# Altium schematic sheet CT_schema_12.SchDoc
size 278 x 170 mm
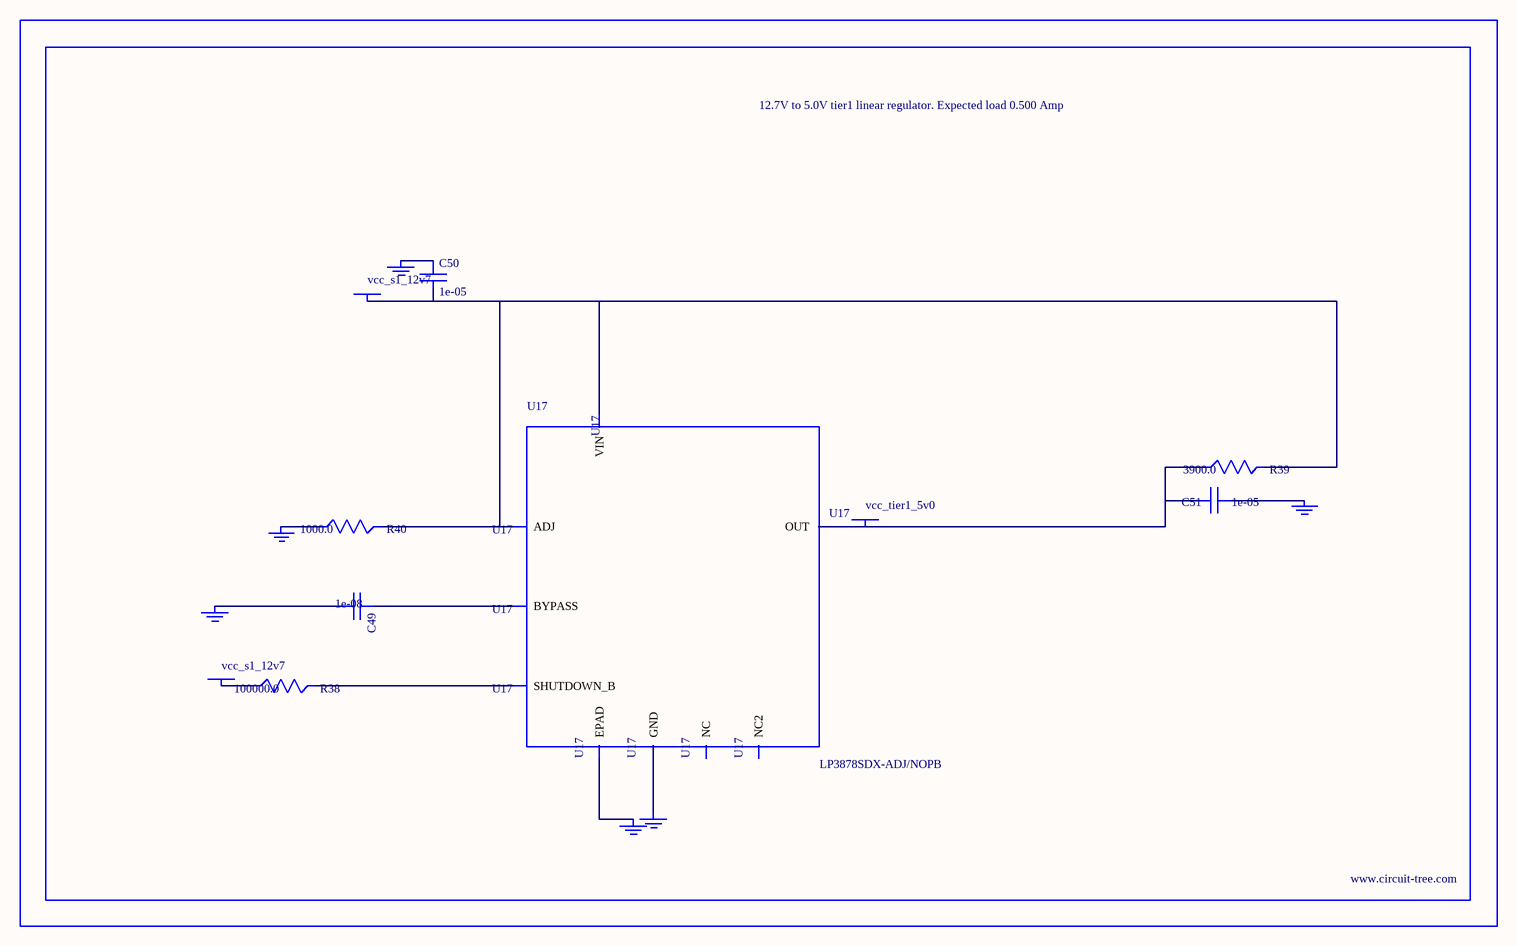
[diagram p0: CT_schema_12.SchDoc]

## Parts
BORDER11  (no value)
C49  1e-08  [C0402]
C50  1e-05  [C1210]
C51  1e-05  [C1210]
GND_INSTANCE_11_0  (no value)
GND_INSTANCE_11_1  (no value)
GND_INSTANCE_11_2  (no value)
GND_INSTANCE_11_3  (no value)
GND_INSTANCE_11_4  (no value)
GND_INSTANCE_11_5  (no value)
POWER_INSTANCE_11_0  vcc_s1_12v7
POWER_INSTANCE_11_1  vcc_s1_12v7
POWER_INSTANCE_11_2  vcc_tier1_5v0
R38  100000.0  [R0603]
R39  3900.0  [R0603]
R40  1000.0  [R0603]
U17  LP3878SDX-ADJ/NOPB  [WSON-8]

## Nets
NetC49_1: C49.1 U17.1(BYPASS)
NetC49_2: C49.2 GND_INSTANCE_11_0.0(GND)
NetC50_1: C50.1 GND_INSTANCE_11_1.0(GND)
NetC50_2: C50.2 POWER_INSTANCE_11_0.0(PWR) R39.2 R40.2 U17.4(VIN) U17.6(ADJ)
NetC51_1: C51.1 GND_INSTANCE_11_2.0(GND)
NetC51_2: C51.2 POWER_INSTANCE_11_2.0(PWR) R39.1 U17.5(OUT)
NetGND_INSTANCE_11_3_0: GND_INSTANCE_11_3.0(GND) R40.1
NetGND_INSTANCE_11_4_0: GND_INSTANCE_11_4.0(GND) U17.PAD(EPAD)
NetGND_INSTANCE_11_5_0: GND_INSTANCE_11_5.0(GND) U17.3(GND)
NetPOWER_INSTANCE_11_1_0: POWER_INSTANCE_11_1.0(PWR) R38.1
NetR38_2: R38.2 U17.8(SHUTDOWN_B)

Not connected (* = marked no-connect by the designer): U17 2(NC) 7(NC2)

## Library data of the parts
BORDER11 = BORDER_PAGE11
C49 = C0402C103K3RAC
C50 = C1210C106K5PACTU
C51 = GRM32DR61E106MA12L
GND_INSTANCE_11_0-GND_INSTANCE_11_5 = GND
POWER_INSTANCE_11_0-POWER_INSTANCE_11_2 = PWR
R38 = RC0603JR-07100KL
R39 = RC0603JR-073K9L
R40 = RC0603JR-071KL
